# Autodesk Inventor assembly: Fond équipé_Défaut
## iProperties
Shininess: 64.0
Length Units: 11269
Angle Units: 11279
Time Units: 11290
Mass Units: 11283
Length Display Precision: 3
Angle Display Precision: 2
Compacted: True
Created: 2006-01
Part Number: Fond équipé_Défaut
Document SubType Name: Assembly
Designer: riri
Density: 0.0
Volumn: 0.0
Area: 0.0
PropertySet Name: Model Information
Control State: 0
Master: False
Checked Out: False
Author: riri
